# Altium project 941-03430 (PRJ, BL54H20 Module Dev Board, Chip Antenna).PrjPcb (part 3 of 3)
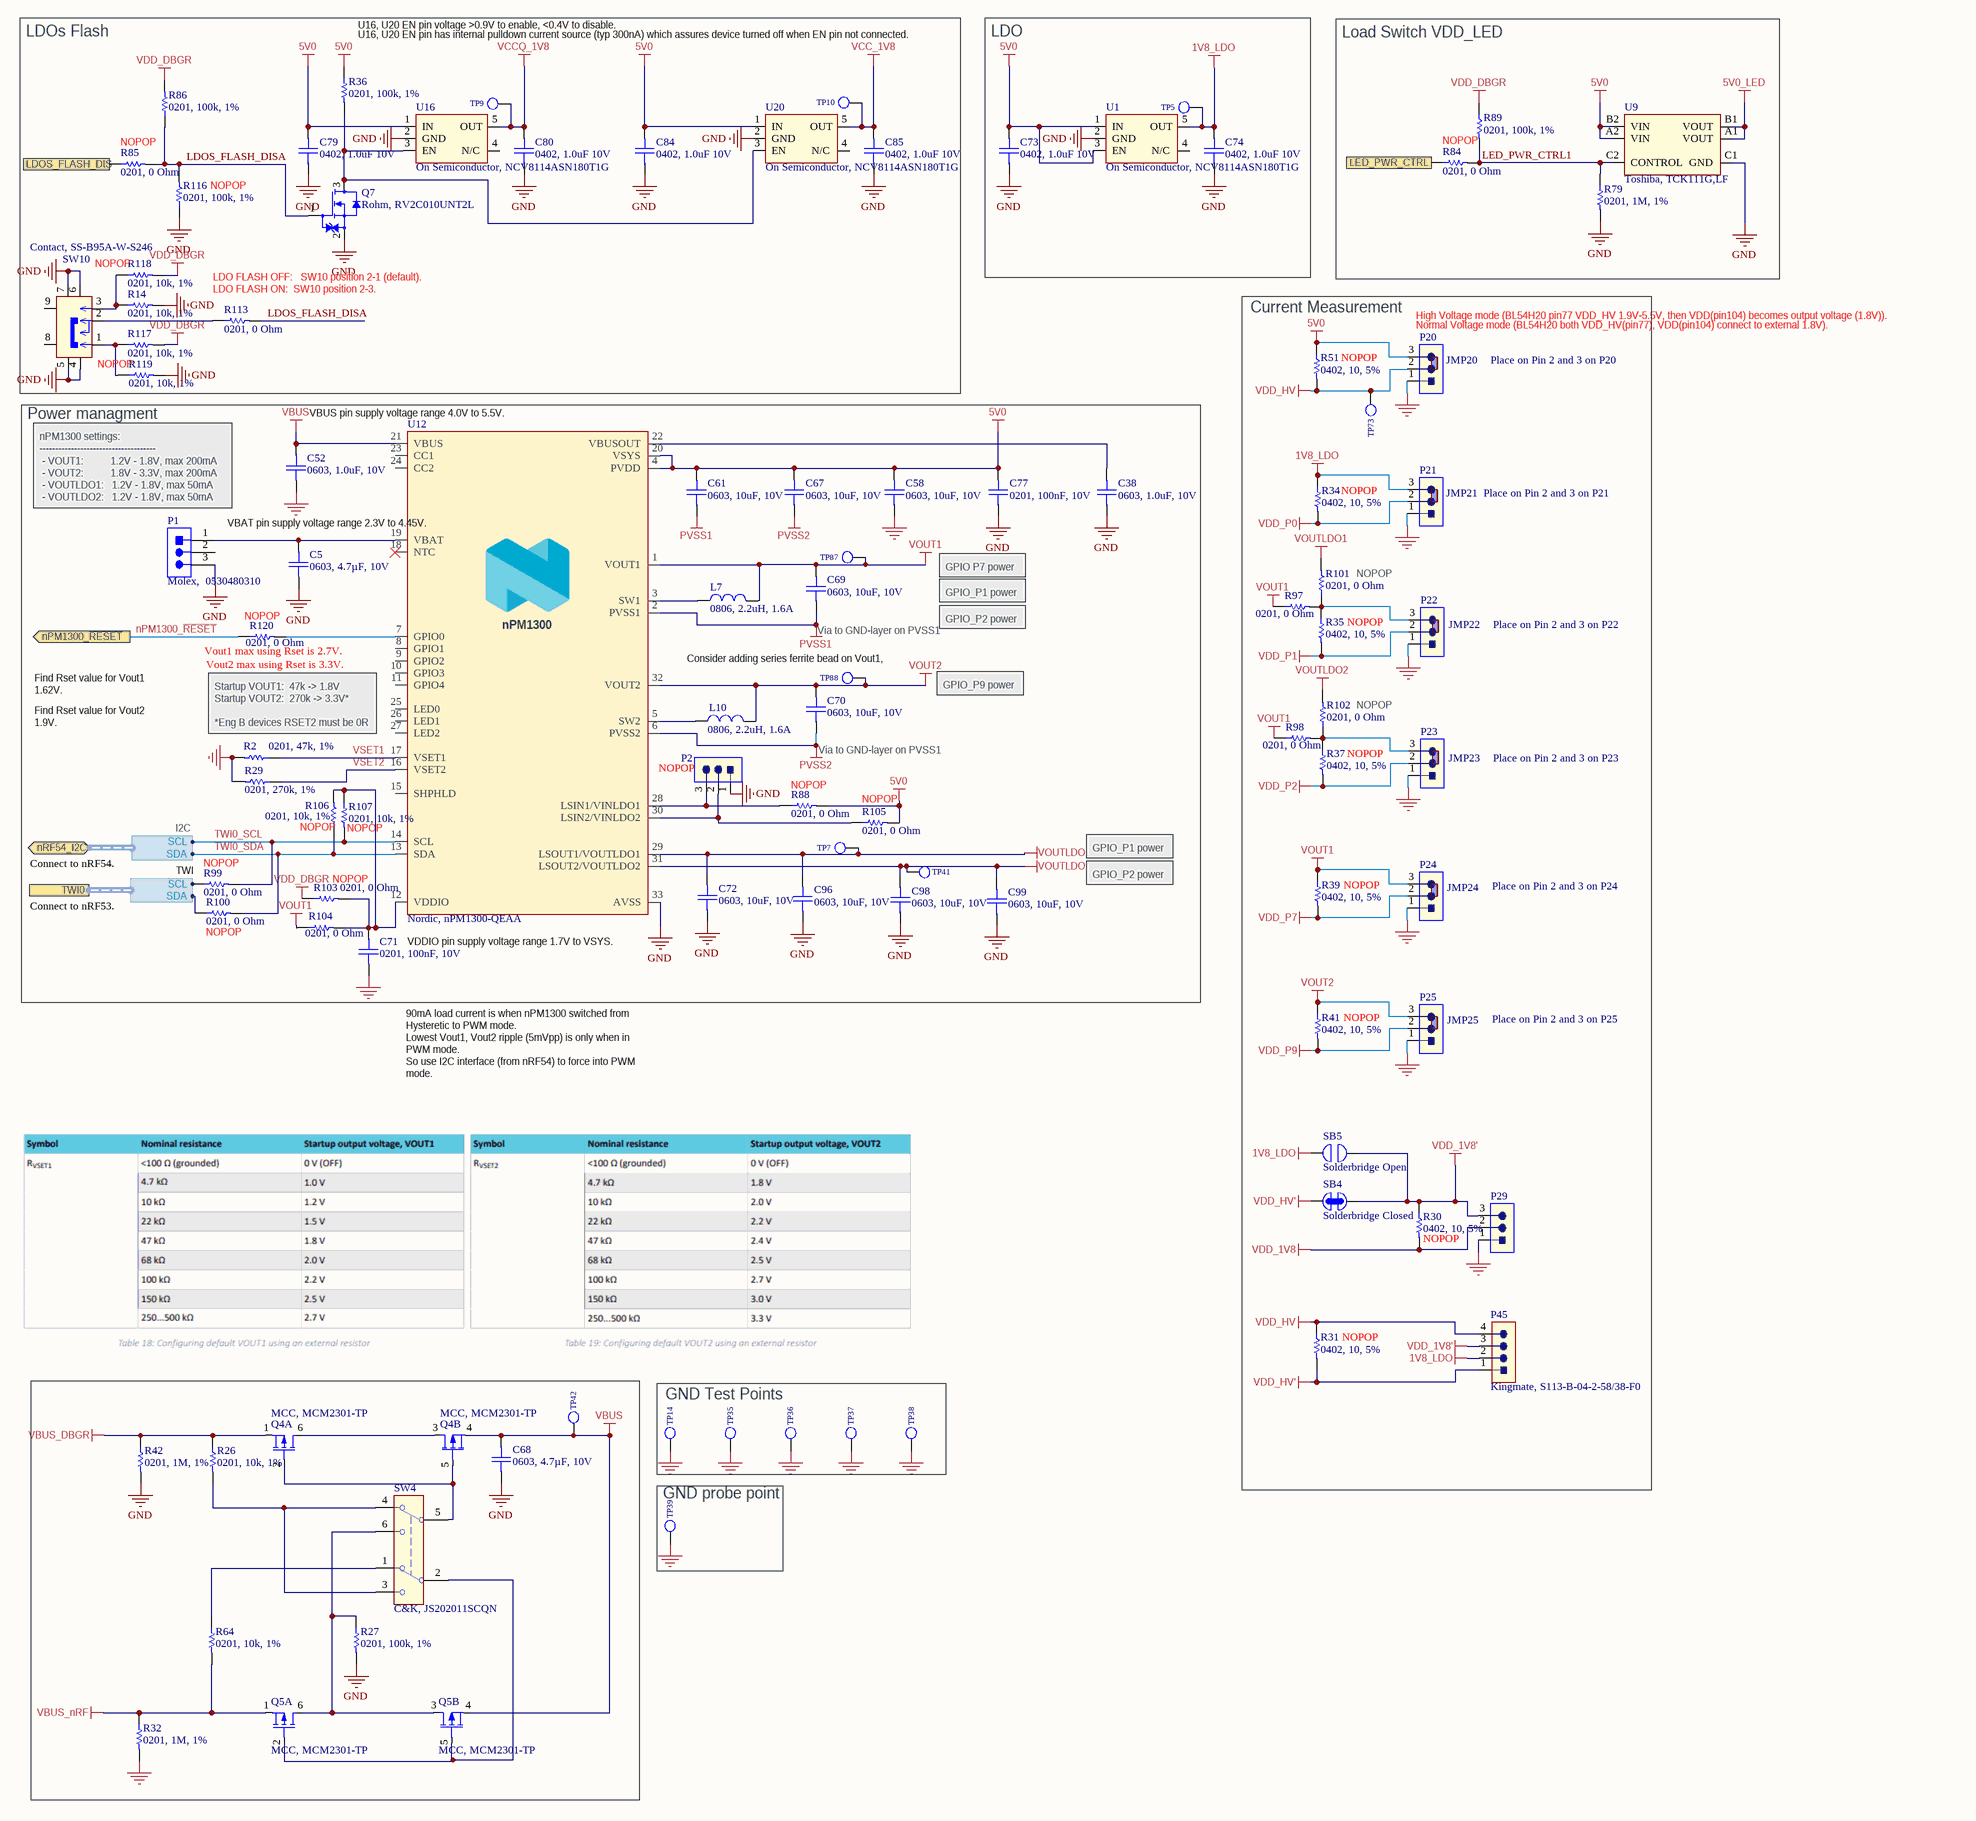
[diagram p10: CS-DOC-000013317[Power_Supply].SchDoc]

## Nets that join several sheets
5V0: CS-DOC-000013317[Connectors] (C4.1 J61.7 U14.1 U14.3), CS-DOC-000013317[Debugger_MCU] (J4.5 R11.1), CS-DOC-000013317[Power_Supply] (20 pins)
5V0_LED: CS-DOC-000013317[Misc] (R20.2 R21.2 R68.2 R69.2), CS-DOC-000013317[Power_Supply] (U9.A1 U9.B1)
GND: CS-DOC-000013317[Connections] (C9.2 S1.1 S1.2), CS-DOC-000013317[Connectors] (59 pins), CS-DOC-000013317[BL54H20] (43 pins), CS-DOC-000013317[Debugger_MCU] (33 pins), CS-DOC-000013317[Level_Shifters] (36 pins), CS-DOC-000013317[Misc] (28 pins), CS-DOC-000013317[Power_Supply] (51 pins)
VBUS_DBGR: CS-DOC-000013317[Connectors] (C90.1 FB2.2), CS-DOC-000013317[Debugger_MCU] (R5.2), CS-DOC-000013317[Power_Supply] (Q4.1 R26.1 R42.1)
VBUS_nRF: CS-DOC-000013317[Connectors] (C87.1 FB1.2), CS-DOC-000013317[BL54H20] (R1.1), CS-DOC-000013317[Power_Supply] (Q5.1 R32.1 R64.2)
VCC_1V8: CS-DOC-000013317[Misc] (C64.1 C76.1 U11.B4), CS-DOC-000013317[Power_Supply] (C85.2 TP10.1 U20.5)
VCCQ_1V8: CS-DOC-000013317[BL54H20] (MOD1.50), CS-DOC-000013317[Misc] (6 pins), CS-DOC-000013317[Power_Supply] (C80.2 TP9.1 U16.5)
VDD_1V8: CS-DOC-000013317[Connectors] (P15.1 P16.1), CS-DOC-000013317[BL54H20] (MOD1.104), CS-DOC-000013317[Power_Supply] (P29.2 R30.2)
VDD_DBGR: CS-DOC-000013317[Debugger_MCU] (30 pins), CS-DOC-000013317[Level_Shifters] (21 pins), CS-DOC-000013317[Misc] (R22.1), CS-DOC-000013317[Power_Supply] (5 pins)
VDD_HV: CS-DOC-000013317[BL54H20] (C3.2 MOD1.77), CS-DOC-000013317[Power_Supply] (5 pins)
VDD_P1: CS-DOC-000013317[Connectors] (C28.2 R78.2 R87.1 U23.C1), CS-DOC-000013317[BL54H20] (MOD1.21), CS-DOC-000013317[Level_Shifters] (C54.2 C55.2 U5.8 U6.8), CS-DOC-000013317[Power_Supply] (P22.2 R35.2)
VDD_P2: CS-DOC-000013317[Connectors] (6 pins), CS-DOC-000013317[BL54H20] (MOD1.83), CS-DOC-000013317[Level_Shifters] (C56.2 C57.2 U3.8 U4.8), CS-DOC-000013317[Power_Supply] (P23.2 R37.2)
VDD_P7: CS-DOC-000013317[Connectors] (C27.2 R77.2 U22.1), CS-DOC-000013317[BL54H20] (MOD1.46), CS-DOC-000013317[Power_Supply] (P24.2 R39.2)
VDD_P9: CS-DOC-000013317[BL54H20] (MOD1.36), CS-DOC-000013317[Power_Supply] (P25.2 R41.2)
VDD_SWD0: CS-DOC-000013317[Connectors] (P19.1 P42.3), CS-DOC-000013317[Level_Shifters] (C59.2 C60.2 U7.8 U8.8)
DBGR_BUTTON: CS-DOC-000013317[Connections] (SB2.2), CS-DOC-000013317[Debugger_MCU] (TP62.1 U2.AL27)
DBGR_N: CS-DOC-000013317[Connectors] (D2.3 J3.A7 J3.B7 TP16.1), CS-DOC-000013317[Debugger_MCU] (U2.B4)
DBGR_P: CS-DOC-000013317[Connectors] (D2.2 J3.A6 J3.B6 TP17.1), CS-DOC-000013317[Debugger_MCU] (U2.B2)
LDOS_FLASH_DIS: CS-DOC-000013317[Debugger_MCU] (TP60.1 U2.B14), CS-DOC-000013317[Power_Supply] (R85.1)
LED_PWR_CTRL: CS-DOC-000013317[Debugger_MCU] (TP82.1 U2.A17), CS-DOC-000013317[Power_Supply] (R84.1)
NFC1: CS-DOC-000013317[Connectors] (J7.2 TP19.1), CS-DOC-000013317[Misc] (C65.1 R24.1)
NFC2: CS-DOC-000013317[Connectors] (J7.4 TP20.1), CS-DOC-000013317[Misc] (C66.1 R25.1)
nPM1300_~{RESET}: CS-DOC-000013317[Debugger_MCU] (TP11.1 U2.AE31), CS-DOC-000013317[Power_Supply] (R120.1)
nRF54_N: CS-DOC-000013317[Connectors] (R43.1), CS-DOC-000013317[BL54H20] (MOD1.28)
nRF54_P: CS-DOC-000013317[Connectors] (R44.1), CS-DOC-000013317[BL54H20] (MOD1.25)
nRF54H20_RESET: CS-DOC-000013317[Connections] (C9.1 S1.3 S1.4 SB3.2), CS-DOC-000013317[Connectors] (P15.10 P16.10), CS-DOC-000013317[BL54H20] (J73.1), CS-DOC-000013317[Level_Shifters] (TP61.1 U13.12)
P0.08: CS-DOC-000013317[BL54H20] (J69.3), CS-DOC-000013317[Misc] (SW2.3 SW2.4)
P0.09: CS-DOC-000013317[BL54H20] (J69.9), CS-DOC-000013317[Misc] (SW3.3 SW3.4)
P0.10: CS-DOC-000013317[BL54H20] (J69.7), CS-DOC-000013317[Misc] (SW5.3 SW5.4)
P0.11: CS-DOC-000013317[BL54H20] (J69.5), CS-DOC-000013317[Misc] (SW6.3 SW6.4)
P1.00: CS-DOC-000013317[Connectors] (C21.2 R33.1 R48.2), CS-DOC-000013317[BL54H20] (J58.8)
P1.01: CS-DOC-000013317[Connectors] (R87.2 U15.2), CS-DOC-000013317[BL54H20] (J58.6)
P1.03: CS-DOC-000013317[Connectors] (U23.D2), CS-DOC-000013317[BL54H20] (J58.10), CS-DOC-000013317[Power_Supply] (R99.2 R107.2 U12.14)
P1.04: CS-DOC-000013317[Connectors] (U23.D1), CS-DOC-000013317[BL54H20] (J58.12), CS-DOC-000013317[Power_Supply] (R100.2 R106.1 U12.13)
P1.07: CS-DOC-000013317[BL54H20] (J58.20), CS-DOC-000013317[Level_Shifters] (R59.1 U6.6)
P1.09: CS-DOC-000013317[BL54H20] (J58.22), CS-DOC-000013317[Level_Shifters] (R58.1 U6.7)
P1.10: CS-DOC-000013317[BL54H20] (J58.24), CS-DOC-000013317[Level_Shifters] (R57.1 U5.6)
P1.11: CS-DOC-000013317[BL54H20] (J58.26), CS-DOC-000013317[Level_Shifters] (R56.1 U5.7)
P2.03: CS-DOC-000013317[Connectors] (U10.4), CS-DOC-000013317[BL54H20] (J70.21)
P2.04: CS-DOC-000013317[BL54H20] (J70.9), CS-DOC-000013317[Level_Shifters] (R53.1 U3.6)
P2.05: CS-DOC-000013317[BL54H20] (J70.11), CS-DOC-000013317[Level_Shifters] (R55.1 U4.6)
P2.06: CS-DOC-000013317[BL54H20] (J70.13), CS-DOC-000013317[Level_Shifters] (R52.1 U3.7)
P2.07: CS-DOC-000013317[BL54H20] (J70.15), CS-DOC-000013317[Level_Shifters] (R54.1 U4.7)
P2.08: CS-DOC-000013317[Connectors] (U21.5), CS-DOC-000013317[BL54H20] (J70.19)
P2.09: CS-DOC-000013317[Connectors] (U21.4), CS-DOC-000013317[BL54H20] (J70.17)
P2.10/NFC_N: CS-DOC-000013317[BL54H20] (MOD1.87 R70.1), CS-DOC-000013317[Misc] (R24.2)
P2.11/NFC_P: CS-DOC-000013317[BL54H20] (MOD1.84 R4.1), CS-DOC-000013317[Misc] (R25.2)
P6.00/CK: CS-DOC-000013317[BL54H20] (MOD1.54), CS-DOC-000013317[Misc] (TP24.1 U11.B2)
P6.02/RWDS: CS-DOC-000013317[BL54H20] (MOD1.55), CS-DOC-000013317[Misc] (TP21.1 U11.C3)
P6.03/CS0: CS-DOC-000013317[BL54H20] (MOD1.51), CS-DOC-000013317[Misc] (R28.2 TP23.1 U11.C2)
P6.04/DQ7: CS-DOC-000013317[BL54H20] (MOD1.52), CS-DOC-000013317[Misc] (TP34.1 U11.E1)
P6.05/DQ1: CS-DOC-000013317[BL54H20] (MOD1.56), CS-DOC-000013317[Misc] (TP26.1 U11.D2)
P6.06/DQ6: CS-DOC-000013317[BL54H20] (MOD1.58), CS-DOC-000013317[Misc] (TP33.1 U11.E2)
P6.07/DQ0: CS-DOC-000013317[BL54H20] (MOD1.60), CS-DOC-000013317[Misc] (TP25.1 U11.D3)
P6.08/DQ5: CS-DOC-000013317[BL54H20] (MOD1.59), CS-DOC-000013317[Misc] (TP32.1 U11.E3)
P6.09/DQ3: CS-DOC-000013317[BL54H20] (MOD1.62), CS-DOC-000013317[Misc] (TP29.1 U11.D4)
P6.10/DQ2: CS-DOC-000013317[BL54H20] (MOD1.64), CS-DOC-000013317[Misc] (TP27.1 U11.C4)
P6.11/DQ4: CS-DOC-000013317[BL54H20] (MOD1.61), CS-DOC-000013317[Misc] (TP31.1 U11.D5)
P6.12/RESETN: CS-DOC-000013317[BL54H20] (MOD1.63), CS-DOC-000013317[Misc] (R23.2 TP22.1 U11.A4)
P7.00: CS-DOC-000013317[Connectors] (U22.4), CS-DOC-000013317[BL54H20] (J71.15)
P7.01: CS-DOC-000013317[Connectors] (U22.5), CS-DOC-000013317[BL54H20] (J71.11)
P7.02: CS-DOC-000013317[Connectors] (U22.3), CS-DOC-000013317[BL54H20] (J71.13)
P7.03: CS-DOC-000013317[Connectors] (P16.12), CS-DOC-000013317[BL54H20] (J71.7)
P7.04: CS-DOC-000013317[Connectors] (P16.14 R114.2), CS-DOC-000013317[BL54H20] (J71.9)
P7.05: CS-DOC-000013317[Connectors] (P16.16 R115.2), CS-DOC-000013317[BL54H20] (J71.1)
P7.06: CS-DOC-000013317[Connectors] (P16.18 R123.2), CS-DOC-000013317[BL54H20] (J71.5)
P7.07: CS-DOC-000013317[Connectors] (P16.20), CS-DOC-000013317[BL54H20] (J71.3)
P9.00: CS-DOC-000013317[BL54H20] (J72.5), CS-DOC-000013317[Misc] (Q2.1 R71.1)
P9.01: CS-DOC-000013317[BL54H20] (J72.9), CS-DOC-000013317[Misc] (Q3.1 R72.1)
P9.02: CS-DOC-000013317[BL54H20] (J72.7), CS-DOC-000013317[Misc] (Q9.1 R73.1)
P9.03: CS-DOC-000013317[BL54H20] (J72.11), CS-DOC-000013317[Misc] (Q10.1 R74.1)
RESET_BUTTON: CS-DOC-000013317[Connections] (SB2.1 SB3.1), CS-DOC-000013317[Misc] (SB1.1 SW1.3 SW1.4)
SWD0_CLK: CS-DOC-000013317[Debugger_MCU] (U2.B18), CS-DOC-000013317[Level_Shifters] (R61.2 U7.3)
SWD0_CLK_EXT: CS-DOC-000013317[Connectors] (P19.4), CS-DOC-000013317[Level_Shifters] (R61.1 U7.6)
SWD0_IO: CS-DOC-000013317[Debugger_MCU] (U2.B16), CS-DOC-000013317[Level_Shifters] (R60.2 U7.2)
SWD0_IO_EXT: CS-DOC-000013317[Connectors] (P19.2), CS-DOC-000013317[Level_Shifters] (R60.1 U7.7)
SWD0_RESET: CS-DOC-000013317[Debugger_MCU] (U2.B22), CS-DOC-000013317[Level_Shifters] (R63.2 U8.3)
SWD0_RESET_EXT: CS-DOC-000013317[Connectors] (P19.10), CS-DOC-000013317[Level_Shifters] (R63.1 U8.6)
SWD0_SELECT: CS-DOC-000013317[Connectors] (P19.3), CS-DOC-000013317[Debugger_MCU] (U2.B24), CS-DOC-000013317[Level_Shifters] (R81.1)
SWD0_SWO: CS-DOC-000013317[Debugger_MCU] (U2.B20), CS-DOC-000013317[Level_Shifters] (R62.2 U8.2)
SWD0_SWO_EXT: CS-DOC-000013317[Connectors] (P19.6), CS-DOC-000013317[Level_Shifters] (R62.1 U8.7)
SWD3_CLK: CS-DOC-000013317[Debugger_MCU] (U2.R1), CS-DOC-000013317[Level_Shifters] (U13.3)
SWD3_CTRL: CS-DOC-000013317[Debugger_MCU] (U2.AB2), CS-DOC-000013317[Level_Shifters] (R83.1)
SWD3_IO: CS-DOC-000013317[Debugger_MCU] (U2.N1), CS-DOC-000013317[Level_Shifters] (U13.15)
SWD3_RESET: CS-DOC-000013317[Debugger_MCU] (U2.AA1), CS-DOC-000013317[Level_Shifters] (U13.11)
SWDCLK: CS-DOC-000013317[Connectors] (P15.4 P16.4), CS-DOC-000013317[BL54H20] (J73.5), CS-DOC-000013317[Level_Shifters] (TP59.1 U13.4)
SWDIO: CS-DOC-000013317[Connectors] (P15.2 P16.2), CS-DOC-000013317[BL54H20] (J73.3), CS-DOC-000013317[Level_Shifters] (TP58.1 U13.16)
TWI0_SCL: CS-DOC-000013317[Debugger_MCU] (U2.AF2), CS-DOC-000013317[Power_Supply] (R99.1)
TWI0_SDA: CS-DOC-000013317[Debugger_MCU] (U2.AE1), CS-DOC-000013317[Power_Supply] (R100.1)
UART0_CTRL: CS-DOC-000013317[Debugger_MCU] (TP45.1 U2.R31), CS-DOC-000013317[Level_Shifters] (R50.1)
UART0_CTS_DBGR: CS-DOC-000013317[Debugger_MCU] (R8.1 U2.AL9), CS-DOC-000013317[Level_Shifters] (R55.2 U4.2)
UART0_HWFC: CS-DOC-000013317[Debugger_MCU] (TP46.1 U2.AK16), CS-DOC-000013317[Level_Shifters] (R65.1)
UART0_RTS_DBGR: CS-DOC-000013317[Debugger_MCU] (U2.AL5), CS-DOC-000013317[Level_Shifters] (R54.2 U4.3)
UART0_RxD_DBGR: CS-DOC-000013317[Debugger_MCU] (U2.AL19), CS-DOC-000013317[Level_Shifters] (R53.2 U3.2)
UART0_TxD_DBGR: CS-DOC-000013317[Debugger_MCU] (U2.U31), CS-DOC-000013317[Level_Shifters] (R52.2 U3.3)
UART1_CTRL: CS-DOC-000013317[Debugger_MCU] (TP51.1 U2.AK18), CS-DOC-000013317[Level_Shifters] (R66.1)
UART1_CTS_DBGR: CS-DOC-000013317[Debugger_MCU] (R9.1 U2.AL15), CS-DOC-000013317[Level_Shifters] (R59.2 U6.2)
UART1_HWFC: CS-DOC-000013317[Debugger_MCU] (TP52.1 U2.AK20), CS-DOC-000013317[Level_Shifters] (R67.1)
UART1_RTS_DBGR: CS-DOC-000013317[Debugger_MCU] (U2.AL13), CS-DOC-000013317[Level_Shifters] (R58.2 U6.3)
UART1_RxD_DBGR: CS-DOC-000013317[Debugger_MCU] (U2.AL21), CS-DOC-000013317[Level_Shifters] (R57.2 U5.2)
UART1_TxD_DBGR: CS-DOC-000013317[Debugger_MCU] (U2.AL23), CS-DOC-000013317[Level_Shifters] (R56.2 U5.3)

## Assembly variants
940-00332(PCBA, BL54H20 Module Dev Board, Chip Antenna): not fitted C1 C6 C7 C9 J4 P2 P16 R3 R4 R10 R28 R30 R31 R34 R35 R37 R39 R41 R50 R51 R52 R53 R54 R55 R56 R57 R58 R59 R60 R61 R62 R63 R65 R66 R67 R70 R81 R82 R83 R84 R85 R88 R99 R100 R101 R102 R103 R105 R106 R107 R116 R118 R119 R120 R121
940-00339(PCBA, BL54H20 Module Dev Board, MHF4): not fitted C1 C6 C7 C9 J4 P2 P16 R3 R4 R10 R28 R30 R31 R34 R35 R37 R39 R41 R50 R51 R52 R53 R54 R55 R56 R57 R58 R59 R60 R61 R62 R63 R65 R66 R67 R70 R81 R82 R83 R84 R85 R88 R99 R100 R101 R102 R103 R105 R106 R107 R116 R118 R119 R120 R121; alternate parts MOD1 -> CMP-MOD-453-00102-1.13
